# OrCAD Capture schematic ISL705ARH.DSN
size B
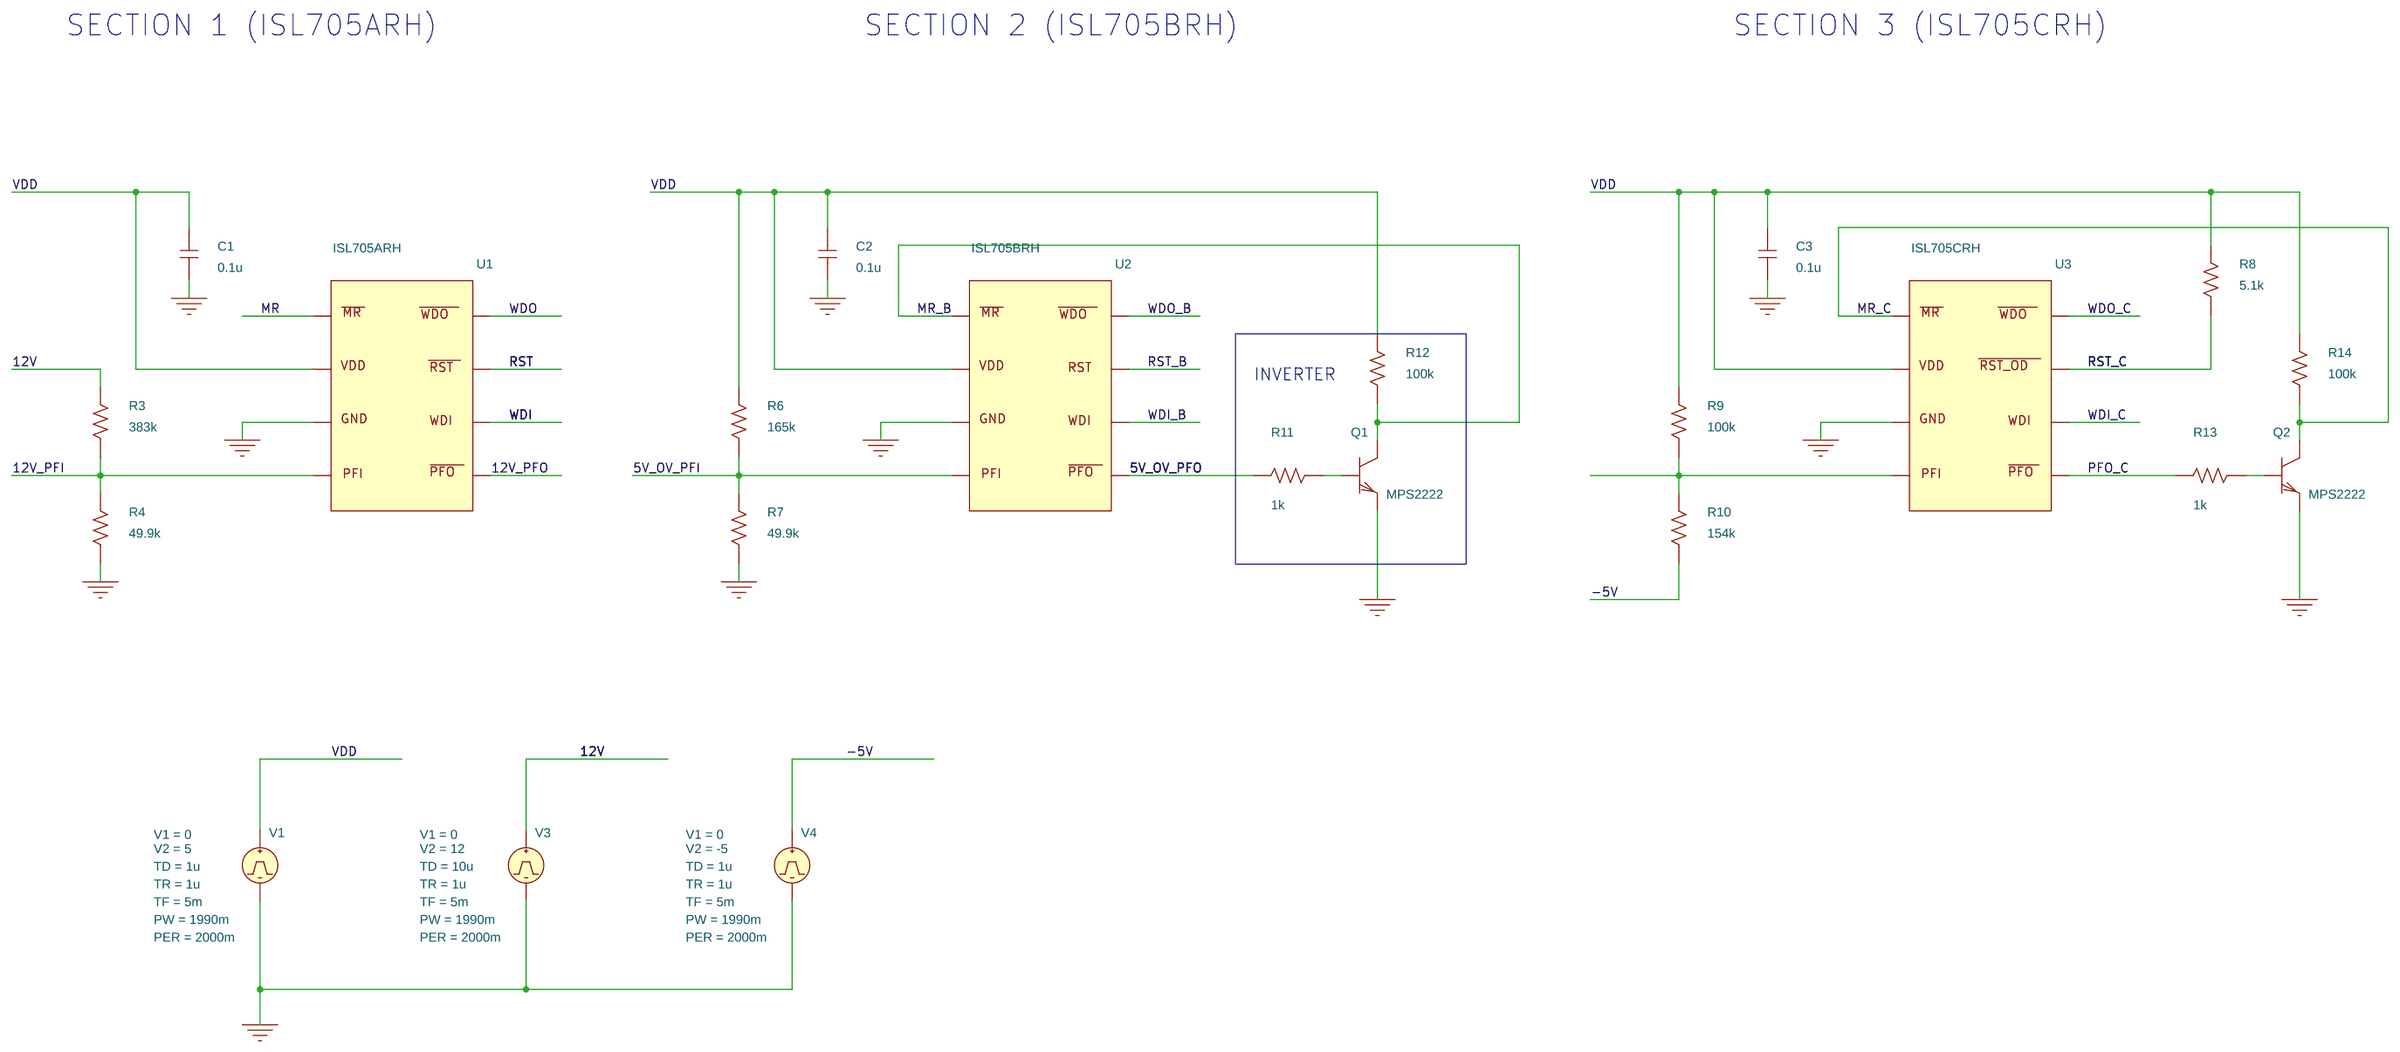
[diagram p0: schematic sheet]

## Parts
C1  0.1u  [RAD/CK05]
C2  0.1u  [RAD/CK05]
C3  0.1u  [RAD/CK05]
Q1  MPS2222  [TO92]
Q2  MPS2222  [TO92]
R3  383k  [AX/RC05]
R4  49.9k  [AX/RC05]
R6  165k  [AX/RC05]
R7  49.9k  [AX/RC05]
R8  5.1k  [AX/RC05]
R9  100k  [AX/RC05]
R10  154k  [AX/RC05]
R11  1k  [AX/RC05]
R12  100k  [AX/RC05]
R13  1k  [AX/RC05]
R14  100k  [AX/RC05]
U1  ISL705ARH
U2  ISL705BRH
U3  ISL705CRH
V1  VPULSE
V3  VPULSE
V4  VPULSE

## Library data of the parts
C1-C3 = C
Q1 Q2 = MPS2222
R3 R4 R6-R14 = R
U1 = ISL705ARH
U2 = ISL705BRH
U3 = ISL705CRH
V1 = VPULSE: PER: 2000m; PW: 1990m; TD: 1u; TF: 5m; TR: 1u; V1: 0; V2: 5
V3 = VPULSE: PER: 2000m; PW: 1990m; TD: 10u; TF: 5m; TR: 1u; V1: 0; V2: 12
V4 = VPULSE: PER: 2000m; PW: 1990m; TD: 1u; TF: 5m; TR: 1u; V1: 0; V2: -5

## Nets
5V_OV_PFI: R6.1 R7.2 U2.4(PFI)
5V_OV_PFO: R11.2 U2.5(N_PFO)
12V: R3.2 V3.1(+)
12V_PFI: R3.1 R4.2 U1.4(PFI)
12V_PFO: U1.5(N_PFO)
-5V: R10.1 V4.1(+)
VDD: C1.2 C2.2 C3.2 R6.2 R8.2 R9.2 R12.2 R14.2 U1.2(VDD) U2.2(VDD) U3.2(VDD) V1.1(+)
0: C1.1 C2.1 C3.1 Q1.1(e) Q2.1(e) R4.1 R7.1 U1.3(GND) U2.3(GND) U3.3(GND) V1.2(-) V3.2(-) V4.2(-)
MR: U1.1(N_MR)
MR_B: Q1.3(c) R12.1 U2.1(N_MR)
MR_C: Q2.3(c) R14.1 U3.1(N_MR)
PFO_C: R13.2 U3.5(N_PFO)
RST: U1.7(N_RST)
RST_B: U2.7(N_RST)
RST_C: R8.1 U3.7(N_RST)
WDI: U1.6(WDI)
WDI_B: U2.6(WDI)
WDI_C: U3.6(WDI)
WDO: U1.8(N_WDO)
WDO_B: U2.8(N_WDO)
WDO_C: U3.8(N_WDO)
N1516028: R9.1 R10.2 U3.4(PFI)
N1630165: Q1.2(b) R11.1
N1647533: Q2.2(b) R13.1

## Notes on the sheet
- SECTION 1 (ISL705ARH)
- SECTION 2 (ISL705BRH)
- SECTION 3 (ISL705CRH)
- INVERTER
